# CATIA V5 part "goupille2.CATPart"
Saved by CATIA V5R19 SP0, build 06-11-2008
Part number: goupille.1.2
Bounding box of the stored display mesh (mm): x 0 to 20, y -2.5 to 2.5, z -2.5 to 2.5
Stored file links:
  C:\Documents and Settings\alenoir\Bureau\mécanisme\goupille2.CATPart
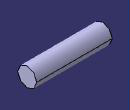
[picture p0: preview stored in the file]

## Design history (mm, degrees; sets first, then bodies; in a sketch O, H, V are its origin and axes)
Body1 (main body)
  Sketch1 on yz-plane, origin (0, 0, 0), H (0, 1, 0), V (0, 0, 1)
    circle A1 centre (0, 0) radius 2.5
    radius A1 = 2.5
  Pad1: profile Sketch1, direction (1, 0, 0), length 20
